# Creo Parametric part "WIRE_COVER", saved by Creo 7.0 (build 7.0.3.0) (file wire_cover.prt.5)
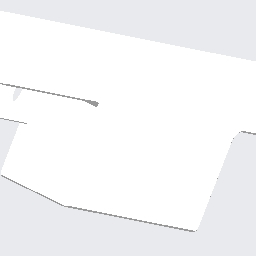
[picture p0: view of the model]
Units: millimeter Kilogram Sec (mmKs); MM, KILOGRAM, SECS

Created from: XX_SOLID_PART_MMKS_ABS.PRT

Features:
  1. coordinate system
  2. datum plane "RIGHT"
  3. datum plane "TOP"
  4. datum plane "FRONT"
  5. extrusion "Extrude 1"
  6. extruded cut "Extrude 2"
  7. extruded cut "Extrude 3"
  8. extruded cut "Extrude 4"
  9. extrusion "Extrude 5"
  10. extrusion "Extrude 6"
  11. extrusion "Extrude 7"
  12. extrusion "Extrude 8"
  13. mirror "Mirror 1"
  14. extrusion "Extrude 8 (2)"
  15. extrusion "Extrude 9"
  16. extrusion "Extrude 10"
  17. extrusion "Extrude 11"
  18. mirror "Mirror 2"
  19. extrusion "Extrude 11 (2)"
  20. round "Round 1"
  21. round "Round 2"
  22. round "Round 3"
  23. round "Round 4"
  24. round "Round 5"
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
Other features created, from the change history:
  chamfer "Chamfer 1"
